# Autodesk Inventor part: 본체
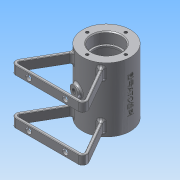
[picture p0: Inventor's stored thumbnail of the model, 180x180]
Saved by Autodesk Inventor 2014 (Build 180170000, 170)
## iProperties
Created: 2016-03
Part Number: 본체
Material: 알루미늄 6061
Document SubType Name: Modeling
Designer: 406-0014
Density: 2.71 g/cm^3
Appearance: 알루미늄 - 평지
Mass: 213.146 g
Surface Area: 333.951 cm^2
Volume: 78.6517 cm^3
Author: 406-0014
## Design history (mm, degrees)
sketch "스케치1"
  geometry: C1 r 26 at (0, 0); 1 further point
  constraints: 1 centre point, 1 coincident
  dimensions: "d0" = 52 diameter of C1
extrude "돌출1" new body sketch "스케치1" distance "d1" = 70; taper "d2" = 0 deg
node "작업 평면1"
sketch "스케치2"
  geometry: L1 (26, 70)-(-26, 70) reference; C1 r 5 at (0, 35); 1 further point
  constraints: 1 centre point
  dimensions: "d5" = 10 diameter of C1; "d6" = 35 distance from line of L1 C1.centre; "d7" = 0 horizontal distance of point (0, 0) C1.centre
extrude "돌출2" join sketch "스케치2" stored distance "d8" = 70; taper "d9" = 0 deg
sketch "스케치3"
  geometry: L1 (26, 70)-(-26, 70) reference; L2 (-26, 0)-(26, 0) reference; L3 (0, 0)-(0, 70); L4 (0, 70)-(16, 70); L5 (16, 70)-(16, 58); L6 (16, 58)-(14, 58); L7 (14, 58)-(14, 56); L8 (14, 56)-(18, 56); L9 (21, 53)-(21, 17); L10 (18, 14)-(14, 14); L11 (14, 14)-(14, 12); L12 (14, 12)-(16, 12); L13 (16, 12)-(16, 0); L14 (16, 0)-(0, 0); A1 r 3 centre (18, 53) between (21, 53) and (18, 56); A2 r 3 centre (18, 17) between (18, 14) and (21, 17); 2 further points
  constraints: 24 end point, 7 perpendicular, 6 point on line, 4 point on circle, 4 tangent, 3 parallel, 2 centre point, 1 equal radius, 1 midpoint
  dimensions: "d10" = 32 diameter of L5 L3; "d11" = 28 diameter of L7 L3; "d12" = 42 diameter of L9 L3; "d13" = 28 diameter of L11 L3; "d14" = 32 diameter of L13 L3; "d15" = 12 distance of L4.end L5.end; "d17" = 12 distance of L13.end L12.end; "d18" = 2 vertical distance of L5.end point (21, 56); "d19" = 2 vertical distance of L12.end point (21, 14); "d20" = 3 radius of A1
revolve "회전1" sketch "스케치3" stored, may be unused: angle "d21" = 90 deg
node "작업 평면3"
  node "작업 평면2"
sketch "스케치7"
  geometry: L1 (0, 33.323)-(0, -33.323); L2 (0, 0)-(-7.506, -28.012); C1 r 26 at (0, 0) reference; 2 further points
  constraints: 4 end point, 2 coincident, 1 midpoint, 1 vertical
  dimensions: "d95" = 15 deg angle of L1 L2; "d96" = 29 distance of L2.start L2.end
sketch "스케치9"
  geometry: C1 r 5 at (0, 0) reference; 2 further points
  constraints: 1 coincident
hole "구멍1" sketch "스케치9" at (0, 0) diameter "d46" = 5.188; stored, may be unused: countersink angle "d50" = 90 deg, drill point angle "d52" = 118 deg; dims "d47" = 19, "d48" = 4, "d49" = 2, "d51" = 20
sketch "스케치11"
  geometry: L1 (34.867, -64.517)-(10.311, -23.868) reference; C1 r 16 at (0, 0) reference; C2 r 21 at (0, 0); 5 further points
  constraints: 1 centre point, 1 coincident, 6 other
  dimensions: "d60" = 42 diameter of C2; "d61" = 21 distance of C1.centre point (0, 21); "d62" = 34.86707 horizontal distance of point (0, 21) L1.start; "d65" = 360 deg dimension on C1.centre point (0, 21) (derived)
hole "구멍3" sketch "스케치11" at (0, 21), (-21, 0), (0, -21), (21, 0) diameter "d67" = 3.242; stored, may be unused: countersink angle "d71" = 90 deg, drill point angle "d73" = 118 deg; dims "d68" = 8, "d69" = 4, "d70" = 2, "d72" = 10
chamfer "모따기1" distance "d74" = 1; stored, may be unused: second distance "d75" = 2, angle "d76" = 45 deg
fillet "모깎기1" dims "d77" = 0.3
fillet "모깎기3" dims "d87" = 2
node "작업 평면5"
node "작업 평면6"
sketch "스케치17"
  geometry: L1 (26, 70)-(-26, 70) reference; L2 (26, 0)-(26, 70) reference; 2 further points
  constraints: 1 other
  dimensions: "d110" = 26 distance from line of L2 point (0, 35); "d111" = 35 distance from line of L1 point (0, 35)
feature "엠보싱1" sketch "스케치17" dims "d10" = 32, "d11" = 28, "d12" = 42, "d13" = 28, "d14" = 32, "d15" = 12, "d17" = 12, "d18" = 2, "d19" = 2, "d20" = 3, "d112" = 0.5, "d113" = 0
sketch "스케치18"
  geometry: L1 (-26, 0)-(26, 0); L2 (-42.594, -65)-(42.594, -65); L3 (0, 26)-(0, -26); L4 (-42.594, -65)-(-16.613, -20); L5 (42.594, -65)-(16.613, -20); A1 r 26 centre (0, 0) between (26, 0) and (-26, 0) reference; 1 further point
  constraints: 10 end point, 6 point on circle, 2 midpoint, 1 horizontal, 1 parallel, 1 perpendicular
  dimensions: "d114" = 65 vertical distance of L2.end L1.end; "d115" = 30 deg angle of L3 L4; "d116" = 30 deg angle of L3 L5; "d117" = 45 vertical distance of L2.end L5.end; "d118" = 45 vertical distance of L2.start L4.end
extrude "돌출10" join sketch "스케치18" distance "d119" = 10; taper "d120" = 0 deg
node "작업 평면7"
fillet "모깎기8" dims "d121" = 5
sketch "스케치21"
  geometry: L1 (-26, 0)-(26, 0); L2 (0, 0)-(-7.506, -28.012); L3 (0, 26)-(0, -26); A1 r 26 centre (0, 0) between (26, 0) and (-26, 0) reference; 3 further points
  constraints: 6 end point, 4 point on circle, 3 midpoint, 1 coincident, 1 horizontal, 1 perpendicular
  dimensions: "d130" = 15 deg angle of L3 L2; "d131" = 29 distance of L2.start L2.end
fillet "모깎기12" dims "d147" = 0.5
sketch "스케치24"
  geometry: L1 (67.868, 0)-(0, 0) reference; L2 (50.154, 44.18)-(71.765, 6.75) reference; L3 (17.321, 44.5)-(-4.33, 7) reference; L4 (19.751, 42.709)-(-1.732, 5.5); L5 (0, 2.5)-(67.868, 2.5); L6 (69.6, 5.5)-(48.117, 42.709); A1 r 4.5 centre (0, 4.5) between (-3.897, 6.75) and (0, 0) reference; A2 r 4.5 centre (67.868, 4.5) between (67.868, 0) and (71.765, 6.75) reference; A3 r 2 centre (0, 4.5) between (-1.732, 5.5) and (0, 2.5); A4 r 2 centre (67.868, 4.5) between (67.868, 2.5) and (69.6, 5.5); A5 r 26 centre (33.934, 64.5) between (19.751, 42.709) and (48.117, 42.709) reference; 2 further points
  constraints: 6 end point, 6 point on circle, 2 centre point, 2 tangent, 1 parallel, 2 other
  dimensions: "d148" = 3 distance between parallel lines of L3 L4
extrude "돌출14" cut sketch "스케치24" distance "d149" = 100; taper "d150" = 0 deg
sketch "스케치25"
  geometry: L1 (67.868, 0)-(0, 0) reference; L2 (0, 9)-(67.868, 9) reference; L3 (33.934, 9)-(33.934, 0); L4 (67.868, 9.5)-(0, 9.5) reference; C1 r 3 at (13.934, 4.5); C2 r 3 at (53.934, 4.5); 1 further point
  constraints: 2 centre point, 2 end point, 2 midpoint, 1 symmetric about line, 1 other
  dimensions: "d151" = 6 diameter of C1; "d152" = 20 horizontal distance of C1.centre L3.start; "d169" = 5 distance from line of L4 C1.centre
extrude "돌출15" cut sketch "스케치25" distance "d154" = 10; taper "d155" = 0 deg
sketch "스케치26"
  geometry: L1 (-26, -35)-(-26, 35) reference; L2 (26, 35)-(-26, 35) reference; C1 r 6 at (0, 0); 1 further point
  constraints: 1 centre point
  dimensions: "d156" = 12 diameter of C1; "d157" = 35 distance from line of C1.centre L2; "d158" = 26 distance from line of C1.centre L1
extrude "돌출16" join sketch "스케치26" stored distance "d159" = 10; taper "d160" = 0 deg
fillet "모깎기13" dims "d161" = 2
sketch "스케치27"
  geometry: C1 r 6 at (0, 0) reference; 2 further points
  constraints: 1 coincident
hole "구멍6" sketch "스케치27" at (0, 0) diameter "d162" = 5.188; stored, may be unused: countersink angle "d166" = 90 deg, drill point angle "d168" = 118 deg; dims "d163" = 19, "d164" = 4, "d165" = 2, "d167" = 20
fillet "모깎기14" dims "d170" = 0.5
fillet "모깎기15" dims "d171" = 3
node "솔리드1"
mirror "대칭2"
mirror "대칭5"
mirror "대칭7"
other parameters: "d3" = 29
